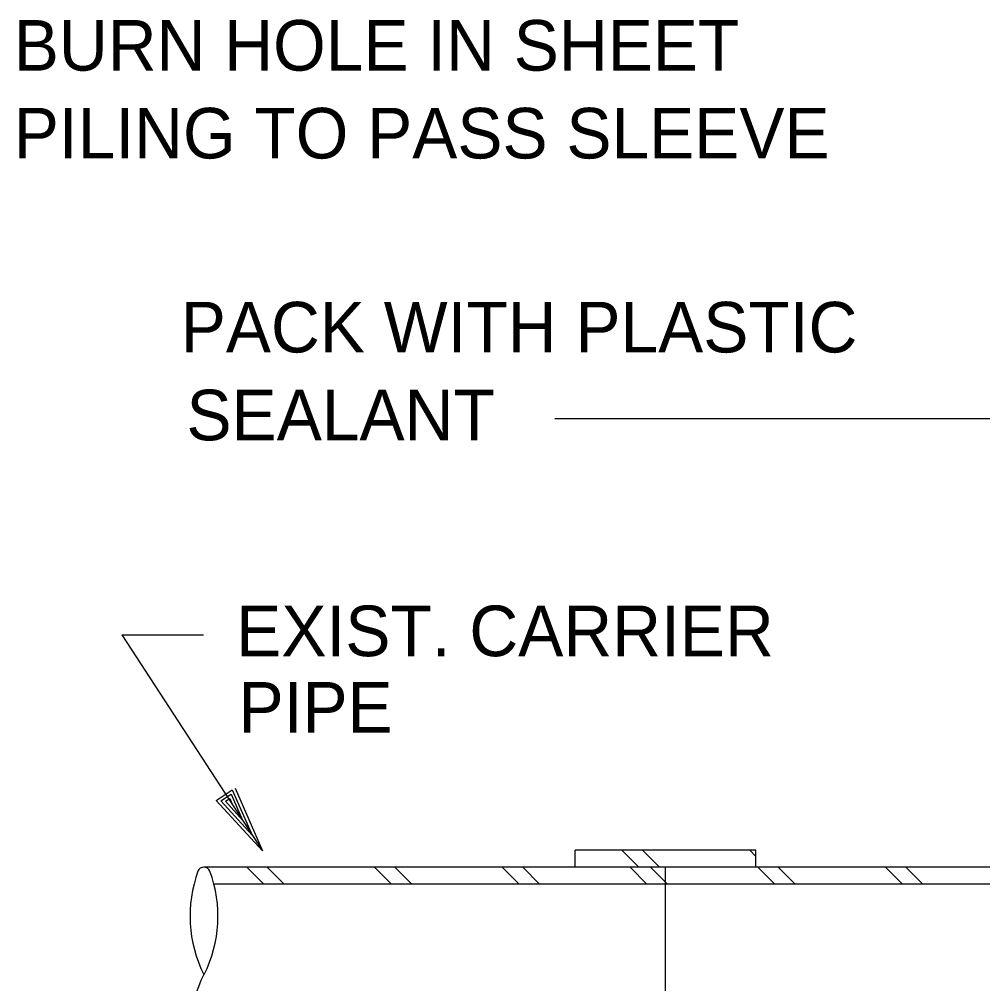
# Model space of a CAD drawing. Extents: x 22411.4 to 22495.4, y 22369.6 to 22415.
# Drawn here: x 22411.406 to 22414.961, y 22392.809 to 22396.368 of the extents above; entities that cross this region are included whole.
import ezdxf

# ---------------------------------------------------------------- set-up
doc = ezdxf.new("R2010")
doc.units = 0
for name, color, linetype in [('Level 1', 7, 'Continuous'), ('Level 2', 7, 'Continuous'), ('Level 4', 7, 'Continuous'), ('Level 8', 7, 'Continuous')]:
    doc.layers.add(name, color=color, linetype=linetype)

msp = doc.modelspace()

# ---------------------------------------------------------------- linework, layer by layer
at = {"layer": 'Level 1'}
for p, q in [((22412.2659, 22393.3573), (22412.2659, 22393.3573)), ((22412.3038, 22393.2992), (22412.3038, 22393.2992))]:
    msp.add_line(p, q, dxfattribs=at)
msp.add_lwpolyline([(22414.1245, 22393.2786), (22414.1015, 22393.3016)], dxfattribs=at)
for centre, radius, start, end in [((22412.0877, 22393.2158), 0.0235, 20.1936, 159.8064), ((22412.516, 22393.0583), 0.4798, 159.8064, 206.6071), ((22411.6595, 22393.0583), 0.4798, 333.3929, 20.1936), ((22412.516, 22392.6285), 0.4798, 153.3929, 200.1919)]:
    msp.add_arc(centre, radius, start, end, dxfattribs=at)
at = {"layer": 'Level 2'}
for p, q in [((22413.3829, 22394.8951), (22415.2997, 22394.8951)), ((22411.7843, 22394.0962), (22412.086, 22394.0962)), ((22411.7843, 22394.0962), (22412.3038, 22393.2992)), ((22413.4578, 22393.2391), (22413.4578, 22393.3016)), ((22414.1245, 22393.3016), (22413.4578, 22393.3016)), ((22414.1245, 22393.2391), (22414.1245, 22393.3016)), ((22417.2912, 22393.2391), (22412.0877, 22393.2391)), ((22413.7912, 22392.4475), (22413.7912, 22393.2391)), ((22417.2912, 22393.1766), (22412.1268, 22393.1766))]:
    msp.add_line(p, q, dxfattribs=at)
msp.add_lwpolyline([(22412.2023, 22393.5306), (22412.3038, 22393.2992), (22412.133, 22393.4855), (22412.1922, 22393.5241), (22412.2659, 22393.3573), (22412.15, 22393.4838), (22412.188, 22393.5086), (22412.2295, 22393.4131), (22412.167, 22393.4822), (22412.1827, 22393.4924), (22412.1917, 22393.4712)], dxfattribs=at)
at = {"layer": 'Level 8'}
for points in [[(22413.6926, 22393.2391), (22413.6301, 22393.3016)], [(22413.768, 22393.2391), (22413.7055, 22393.3016)], [(22412.3081, 22393.1766), (22412.2456, 22393.2391)], [(22412.3835, 22393.1766), (22412.321, 22393.2391)], [(22412.7795, 22393.1766), (22412.717, 22393.2391)], [(22412.8549, 22393.1766), (22412.7924, 22393.2391)], [(22413.2509, 22393.1766), (22413.1884, 22393.2391)], [(22413.3263, 22393.1766), (22413.2638, 22393.2391)], [(22413.7223, 22393.1766), (22413.6598, 22393.2391)], [(22413.7977, 22393.1766), (22413.7352, 22393.2391)], [(22414.1937, 22393.1766), (22414.1312, 22393.2391)], [(22414.2691, 22393.1766), (22414.2066, 22393.2391)], [(22414.6651, 22393.1766), (22414.6026, 22393.2391)], [(22414.7405, 22393.1766), (22414.678, 22393.2391)]]:
    msp.add_lwpolyline(points, dxfattribs=at)

# ---------------------------------------------------------------- texts
at = {"layer": 'Level 4'}
for s, height, p in [('BURN HOLE IN SHEET', 0.186667, (22411.3859, 22396.1781)), ('PILING TO PASS SLEEVE', 0.186667, (22411.3859, 22395.854)), ('PACK WITH PLASTIC', 0.186667, (22412.002, 22395.1382)), ('SEALANT', 0.18667, (22412.0232, 22394.8141)), ('EXIST. CARRIER', 0.186667, (22412.2069, 22394.0176)), ('PIPE', 0.18667, (22412.2154, 22393.7354))]:
    msp.add_text(s, height=height, dxfattribs=at).set_placement(p)

doc.saveas('drawing.dxf')
